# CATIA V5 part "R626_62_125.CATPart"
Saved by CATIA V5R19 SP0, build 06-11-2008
Material "Steel": density 7860 kg/m3, Young's modulus 2e+11 Pa, Poisson ratio 0.266, thermal expansion 1.17e-05 1/K
Bounding box of the stored display mesh (mm): x -66.868 to 66.014, y -66.941 to 66.937, z -0.022 to 63
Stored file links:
  G:\Podręcznik\CD\Narzędzia\Arkusz Excel\Modele narzędzi\R626.62-125.CATPart
  C:\Program Files\Dassault Systemes\B19\intel_a\startup\materials\Catalog.CATMaterial
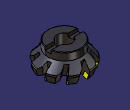
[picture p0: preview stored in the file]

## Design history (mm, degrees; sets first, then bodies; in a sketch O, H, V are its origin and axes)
Parameters
  CuttingType = "CUTTER"
Body1 "BODY" (main body), material "Steel"
  Sketch1 on yz-plane, origin (0, 0, 0), H (0, 1, 0), V (0, 0, 1)
    point P1 (20, 63)
    line L1 (20, 63) -> (43.5858, 63)
    line L2 (43.5858, 63) -> (45, 61.5858)
    line L3 (45, 61.5858) -> (45, 43)
    point P4 (45, 43)
    line L4 (45, 43) -> (67.3941, 19.6008)
    line L5 (67.3941, 19.6008) -> (62.2177, 0.2823)
    point P6 (62.2177, 0.2823)
    line L6 (62.2177, 0.2823) -> (32.5, 8.2451)
    line L7 (32.5, 8.2451) -> (32.5, 28.5)
    line L8 (32.5, 28.5) -> (20, 28.5)
    line L9 (20, 28.5) -> (20, 63)
    point P10 (20, 63)
    axis line L10 (62.5, 3.8987) -> (62.5, 0.2823)
    distance L8 L1 = 34.5
    distance V L9 = 20
    distance L1 H = 63
    angle H L5 = 75
    distance L7 V = 32.5
    distance P4 L1 = 20
    length L2 = 2
    distance V L3 = 45
    angle L3 L2 = 45
    angle L5 L6 = 90
    length L5 = 20
    distance P6 H = 0.2823
    distance L10 V = 62.5
    distance L10 P6 = 0.2823
    horizontal: L1 H, L8 H
    vertical: L3 V, L7 V, L9 V, L10 V
    coincidence: P10 L1, P1 P10
  Shaft1: profile Sketch1, axis Z axis, angle 360
  Sketch2 on yz-plane, origin (0, 0, 0), H (0, 1, 0), V (0, 0, 1)
    line L1 (-8.2, 63) -> (8.2, 63)
    line L2 (8.2, 63) -> (8.2, 54)
    line L3 (8.2, 54) -> (-8.2, 54)
    line L4 (-8.2, 54) -> (-8.2, 63)
    reference projected line E1 (-43.5858, 63) -> (43.5858, 63) from edge [face of Shaft1 from Sketch1.L2 | face of Shaft1 from Sketch1.L1]
    length L1 = 16.4
    length L2 = 9
    distance L2 V = 8.2
    horizontal: L1 H, L3 H
    vertical: L2 V, L4 V
    coincidence: L1 E1
  Pocket1: profile Sketch2, direction (-1, 0, 0), length 50, mirrored extent
  Sketch3 on xy-plane, origin (0, 0, 0), H (1, 0, 0), V (0, 1, 0)
    point P1 (0, 62.2177)
    reference projected circle E1 centre (0, 0) radius 62.2177 from edge [face of Shaft1 from Sketch1.L6 | face of Shaft1 from Sketch1.L5]
    coincidence: P1 V, P1 E1
  Plane1: type Tangent, Support face of Shaft1 from Sketch1.L6, RefPoint Sketch3
  Sketch4 on Plane1, origin (0, 4.1678, 15.5544), H (-1, 0, 0), V (0, -0.9659, 0.2588)
    point P1 (-1.4174, -60.009)
    line L1 (-1.4174, -60.009) -> (0.5, -38.0927)
    point P2 (0.5, -38.0927)
    line L2 (0.5, -38.0927) -> (-9.5, -38.0927)
    line L3 (-9.5, -38.0927) -> (-13.6042, -49.369)
    line L4 (-13.6042, -49.369) -> (-26.2833, -57.3842)
    point P5 (-26.2833, -57.3842)
    reference projected curve E1 from edge [face of Shaft1 from Sketch1.L6 | face of Shaft1 from Sketch1.L5]
    line L5 (-12.1646, -68.5494) -> (-2.1646, -68.5494)
    point P7 (-2.1646, -68.5494)
    line L6 (-2.1646, -68.5494) -> (-1.4174, -60.009)
    point P8 (-26.2833, -57.3842)
    line L7 (-26.2833, -57.3842) -> (-12.1646, -68.5494)
    length L2 = 10
    length L3 = 12
    length L4 = 15
    length L1 = 22
    angle L1 L2 = 85
    distance P2 V = 0.5
    angle V L1 = 5
    angle L2 L3 = 110
    length L5 = 10
    length L7 = 18
    distance P5 L6 = 25
    coincidence: P1 E1, P7 L1, P5 P8
    horizontal: L5 H
    parallelism: L6 L1
  Sketch5 on yz-plane, origin (0, 0, 0), H (0, 1, 0), V (0, 0, 1)
    line L1 (63.2564, 28.0434) -> (69, 12.263)
    point P2 (69, 12.263)
    line L2 (69, 12.263) -> (81.3291, 12.263)
    line L3 (81.3291, 12.263) -> (81.3291, 28.0434)
    line L4 (81.3291, 28.0434) -> (63.2564, 28.0434)
    distance P2 V = 69
    angle L1 L2 = 70
    horizontal: L2 H, L4 H
    vertical: L3 V
  Groove1: profile Sketch5, axis Z axis, angle 360
  Plane2: type Tangent, Support face of Shaft1 from Sketch1.L5, RefPoint Sketch3
  Sketch6 on Plane2, origin (0, 58.0499, -15.5544), H (1, 0, 0), V (0, 0.2588, 0.9659)
    point P1 (-0.5, 16.1031)
    line L1 (-0.5, 16.1031) -> (-3.2642, 38.6158)
    reference projected point E1 (-0.5, 16.1031) from vertex [element of Sketch4 | element of Sketch4]
    angle V L1 = 7
    coincidence: P1 E1
  Pocket2: profile Sketch4, direction along Sketch6.L1 reversed, length 35, mirrored extent
  CircPattern1: of Pocket2, instances 9, angular step 40, axis from Z axis
  Plane3: type Tangent, Support face of Shaft1 from Sketch1.L5, RefPoint vertex [face of Pocket2 from Sketch4.L6 | face of Pocket2 from Sketch4.L1 | face of Shaft1 from Sketch1.L5 | face of Shaft1 from Sketch1.L6]
  Sketch7 on Plane3, origin (1.2902, 57.965, -15.5355), H (0.9998, -0.0223, 0), V (0.0058, 0.2588, 0.9659)
    line L1 (0.0134, 16.2713) -> (-1.6984, 29.5857)
    point P1 (0.0134, 16.2713)
    reference projected line E1 (-2.3458, 34.6207) -> (0, 16.3758) from edge [face of Pocket2 from Sketch4.L6 | face of Shaft1 from Sketch1.L5]
    coincidence: L1 E1
  Plane4: type Angle, Angle 11, Direction Sketch7, RefPlane Plane3
  Plane5: type Offset, Offset 0.2823, RefPlane Plane4, reversed
  Sketch8 on face of Pocket2 from Sketch4.L1, origin (-1.8142, 0.0957, -0.2562), H (0.0527, 0.9986, 0), V (-0.1395, 0.0074, 0.9902)
    line L1 (50.912, 3.6984) -> (54.2813, 16.5964)
    reference intersected line E1 through (58.3657, -15.2466) direction (-0.2527, -0.9675) from Plane5
    reference intersected line E2 through (58.3657, -15.2466) direction (-0.2527, -0.9675) from Plane5
    distance E2 L1 = 12
    parallelism: E1 L1
  Plane6: type Offset, Offset 12, RefPlane Plane5
  Plane7: type Angle, Angle -22, Direction Sketch8, RefPlane Plane6
  Plane8: type Tangent, Support face of Pocket2 from Sketch4.L1, RefPoint Sketch7.P1
  Plane9: type Angle, Angle 90, Direction Sketch7, RefPlane Plane8
  Sketch9 on Plane9, origin (5.1744, 57.8923, -15.0221), H (0.996, -0.089, 0), V (0.0223, 0.2492, 0.9682)
    line L1 (-5.5723, 27.4626) -> (-8.6299, 26.3922)
    line L2 (-8.6299, 26.3922) -> (-7.0772, 15.7411)
    point P3 (-7.0772, 15.7411)
    line L3 (-7.0772, 15.7411) -> (-3.8413, 15.5881)
    line L4 (-3.8413, 15.5881) -> (-5.5723, 27.4626)
    construction line L5 (-5.5723, 27.4626) -> (-123.4933, 10.2721)
    axis line L6 (-113.0645, 20.7501) -> (-120.8351, 19.6173)
    point P6 (-113.0645, 20.7501)
    reference projected curve E1 from edge [face of Shaft1 from Sketch1.L6 | face of Shaft1 from Sketch1.L5]
    reference projected line E2 (-6.8121, 34.0099) -> (-4.1585, 15.8073) from edge [face of Pocket2 from Sketch4.L6 | face of Shaft1 from Sketch1.L5]
    reference projected line E3 (-6.8121, 34.0099) -> (-4.1585, 15.8073) from edge [face of Pocket2 from Sketch4.L6 | face of Shaft1 from Sketch1.L5]
    distance L2 L4 = 3.18
    length L4 = 12
    angle L1 L5 = 11
    angle L6 L3 = 11
    distance E3 L4 = 0.2823
    perpendicularity: L5 L2
    coincidence: P6 L3, P3 E1
    parallelism: L6 L5, L4 E2
  Pocket3: profile Sketch9, direction (0.0862, 0.9643, -0.2502), up to Plane7, opposite side up to Plane9
  CircPattern2: of Pocket3, instances 9, angular step 40, axis from Z axis
Body2 "INSERTS"
  Pad1: profile Sketch9, direction (-0.0862, -0.9643, 0.2502), up to Plane7, opposite side up to Plane5
  CircPattern3: of Pad1, instances 9, angular step 40, axis from Z axis
  Sketch10 "CUT" on yz-plane, origin (0, 0, 0), H (0, 1, 0), V (0, 0, 1)
    line L1 (50.9089, 3.1058) -> (62.5, 0)
    point P2 (62.5, 0)
    line L2 (62.5, 0) -> (65.6058, 11.5911)
    line L3 (65.6058, 11.5911) -> (54.0147, 14.6969)
    line L4 (54.0147, 14.6969) -> (50.9089, 3.1058)
    length L2 = 12
    length L3 = 12
    angle L4 L3 = 90
    angle L2 L1 = 90
    distance P2 V = 62.5
    angle L2 H = 75
    perpendicularity: L3 L2
    coincidence: P2 H
  Sketch11 "NOCUT" on yz-plane, origin (0, 0, 0), H (0, 1, 0), V (0, 0, 1)
    construction line L1 through (-0.119, 0) direction (1, 0)
    construction line L2 through (0, 3.8026) direction (0, 1)
    point P5 (0, 28.5)
    line L3 (0, 28.5) -> (32.5, 28.5)
    line L4 (32.5, 28.5) -> (32.5, 8.3307)
    line L5 (32.5, 8.3307) -> (50.982, 3.3785)
    line L6 (50.982, 3.3785) -> (54.0147, 14.6969)
    line L7 (54.0147, 14.6969) -> (65.3331, 11.6642)
    line L8 (65.3331, 11.6642) -> (67.0083, 17.9158)
    point P11 (67.0083, 17.9158)
    line L9 (67.0083, 17.9158) -> (65.5789, 21.3962)
    point P12 (65.5789, 21.3962)
    line L10 (65.5789, 21.3962) -> (45, 43)
    point P13 (45, 43)
    line L11 (45, 43) -> (45, 61.5858)
    line L12 (45, 61.5858) -> (43.5858, 63)
    line L13 (43.5858, 63) -> (0, 63)
    point P16 (0, 63)
    line L14 (0, 63) -> (0, 28.5)
    construction line L15 (54.0147, 14.6969) -> (65.6058, 11.5911)
    construction line L16 (65.6058, 11.5911) -> (62.5, 0)
    point P18 (62.5, 0)
    construction line L17 (54.0147, 14.6969) -> (50.9089, 3.1058)
    axis line L18 (50.9089, 3.1058) -> (62.5, 0)
    reference projected line E1 (-45, 43) -> (45, 43) from edge [face of Shaft1 from Sketch1.L4 | face of Shaft1 from Sketch1.L3]
    reference projected line E2 (65.6758, 21.3962) -> (-65.6758, 21.3962) from edge [face of Shaft1 from Sketch1.L4 | face of Groove1 from Sketch5.L1]
    reference projected line E3 (-66.9426, 17.9158) -> (66.9426, 17.9158) from edge [face of Shaft1 from Sketch1.L5 | face of Groove1 from Sketch5.L1]
    distance L11 L14 = 45
    length L16 = 12
    length L15 = 12
    length L17 = 12
    distance L8 L16 = 0.2823
    distance L18 L5 = 0.2823
    distance P18 L2 = 62.5
    angle L1 L8 = 75
    length L3 = 32.5
    distance L1 L13 = 63
    length L12 = 2
    distance L13 L3 = 34.5
    angle L11 L12 = 45
    angle L10 L9 = 158.7188
    coincidence: P5 L2, P16 L2, L2 V, H L1, P18 L1, P13 E1, P12 E2, P11 E3
    horizontal: L3 H, L13 H
    vertical: L4 V, L11 V, L14 V
    perpendicularity: L6 L5
    parallelism: L7 L5, L8 L6, L15 L7, L17 L6, L18 L15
